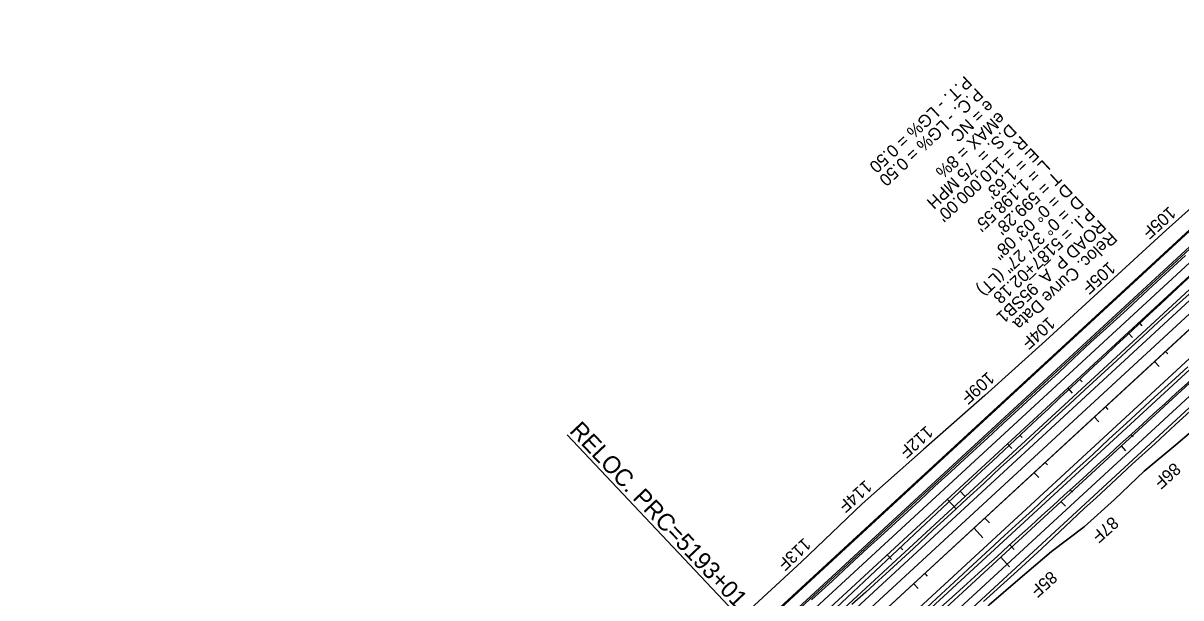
# Model space of a CAD drawing. Extents: x 2160876 to 2175990, y 601436 to 618246.
# Drawn here: x 2169726 to 2171138, y 612405 to 613107 of the extents above; entities that cross this region are included whole.
import ezdxf

# ---------------------------------------------------------------- set-up
doc = ezdxf.new("R2010")
doc.units = 0
for name, color, linetype in [('BNDY-ADJ', 7, 'Continuous'), ('BNDY-ADJ-TXT', 7, 'Continuous'), ('EX-UTIL-ELEC-TXT', 7, 'Continuous'), ('GN_Transparent 80', 7, 'Continuous'), ('RD_DTM_Major2', 7, 'Continuous'), ('RD_EX_BldgApp_Sign', 7, 'Continuous'), ('RD_EX_BldgApp_Steps', 7, 'Continuous'), ('RD_EX_Fence_Gate', 7, 'Continuous'), ('RD_EX_RW', 7, 'Continuous'), ('RD_HC_Cl', 7, 'Continuous'), ('RD_TX_RoadID', 7, 'Continuous')]:
    doc.layers.add(name, color=color, linetype=linetype)

msp = doc.modelspace()

# ---------------------------------------------------------------- linework, layer by layer
at = {"layer": 'BNDY-ADJ'}
msp.add_line((2172239.9, 613739.9), (2163704.8, 605858.6), dxfattribs=at)
at = {"layer": 'BNDY-ADJ-TXT'}
for p, q in [((2172207.3, 613775.1), (2170395.2, 612101.8)), ((2172272.5, 613704.6), (2170460.3, 612031.3))]:
    msp.add_line(p, q, dxfattribs=at)
at = {"layer": 'EX-UTIL-ELEC-TXT'}
for p, q in [((2172179.3, 613805.5), (2170367.1, 612132.2)), ((2172180, 613804.8), (2170367.8, 612131.4)), ((2172199.2, 613784), (2170387, 612110.6)), ((2172207.3, 613775.1), (2170395.2, 612101.8)), ((2172215.5, 613766.3), (2170403.3, 612093)), ((2172264.3, 613713.4), (2170452.2, 612040.1)), ((2172272.5, 613704.6), (2170460.3, 612031.3)), ((2172261.1, 613677.8), (2170468.4, 612022.5))]:
    msp.add_line(p, q, dxfattribs=at)
at = {"layer": 'GN_Transparent 80'}
for p, q in [((2172189.5, 613794.5), (2170377.3, 612121.1)), ((2172191, 613792.8), (2170378.9, 612119.4))]:
    msp.add_line(p, q, dxfattribs=at)
at = {"layer": 'RD_DTM_Major2'}
for p, q in [((2171106.4, 612693.2), (2171111.8, 612687.3)), ((2171032.9, 612625.4), (2171038.4, 612619.5)), ((2170959.5, 612557.5), (2170964.9, 612551.7)), ((2170886, 612489.7), (2170896.9, 612477.9)), ((2170812.5, 612421.9), (2170818, 612416))]:
    msp.add_line(p, q, dxfattribs=at)
at = {"layer": 'RD_EX_BldgApp_Sign'}
msp.add_line((2170418.2, 612076.8), (2171614.4, 613181.4), dxfattribs=at)
at = {"layer": 'RD_EX_BldgApp_Steps'}
for p, q in [((2172672.7, 614139.6), (2163700.6, 605854.7)), ((2171088.2, 612739.8), (2171090.9, 612736.9)), ((2171119.8, 612705.6), (2171122.5, 612702.7)), ((2171015.1, 612671.5), (2171017.8, 612668.6)), ((2171046.4, 612637.8), (2171049.1, 612634.8)), ((2170389.5, 612603.9), (2170649.6, 612328.2)), ((2170942.1, 612603.2), (2170944.8, 612600.3)), ((2171077.5, 612604), (2171080.1, 612601.1)), ((2170972.9, 612569.9), (2170975.6, 612567)), ((2170869.2, 612534.8), (2170874.6, 612529)), ((2171003.5, 612536.7), (2171006.2, 612533.7)), ((2170899.4, 612502.1), (2170904.9, 612496.2)), ((2170796.3, 612466.3), (2170799, 612463.4)), ((2170929.6, 612469.4), (2170935, 612463.5)), ((2170826, 612434.2), (2170828.7, 612431.3))]:
    msp.add_line(p, q, dxfattribs=at)
for centre, start, end in [((2246150.8, 532330.8), 132.719474, 133.343763), ((2096943.5, 693870), 312.103138, 312.719474)]:
    msp.add_arc(centre, 110000, start, end, dxfattribs=at)
at = {"layer": 'RD_EX_Fence_Gate'}
for p, q in [((2171194.8, 612920.4), (2171120.6, 612853.6)), ((2171120.6, 612853.6), (2171047, 612786.1)), ((2171047, 612786.1), (2170973.3, 612718.7)), ((2170973.3, 612718.7), (2170899.3, 612651.6)), ((2170899.3, 612651.6), (2170824.3, 612585.7)), ((2170824.3, 612585.7), (2170749.7, 612519.3)), ((2170749.7, 612519.3), (2170675.7, 612448.7)), ((2170675.7, 612448.7), (2170602.4, 612380.9))]:
    msp.add_line(p, q, dxfattribs=at)
msp.add_lwpolyline([(2171170.3, 612624.1), (2171132.3, 612591.5), (2171093.8, 612559.5), (2171057.6, 612524.9), (2171020.5, 612491.5), (2170980.4, 612461.2), (2170942.5, 612428.5), (2170904.5, 612395.9), (2170868.6, 612361.2), (2170832.6, 612326.4), (2170796, 612292.4), (2170759.1, 612258.7), (2170724.9, 612221.9), (2170684.4, 612192.1), (2170653.3, 612152.1), (2170617.1, 612117.6), (2170580.6, 612083.5), (2170544, 612049.4), (2170507.9, 612014.8), (2170472.7, 611979.1), (2170437.2, 611943.9), (2170400.6, 611909.8), (2170363.7, 611876.2)], dxfattribs=at)
at = {"layer": 'RD_EX_RW'}
for p, q in [((2171194.8, 612920.4), (2171120.6, 612853.6)), ((2171120.6, 612853.6), (2171047, 612786.1)), ((2171047, 612786.1), (2170973.3, 612718.7)), ((2170973.3, 612718.7), (2170899.3, 612651.6)), ((2170899.3, 612651.6), (2170824.3, 612585.7)), ((2170824.3, 612585.7), (2170749.7, 612519.3)), ((2170749.7, 612519.3), (2170675.7, 612448.7)), ((2170675.7, 612448.7), (2170602.4, 612380.9))]:
    msp.add_line(p, q, dxfattribs=at)
for points in [[(2170687.8, 612402), (2170713.1, 612425.2), (2170733.8, 612444.4), (2170756.2, 612465.2), (2170776, 612483.4), (2170795.4, 612501.2), (2170819.8, 612523.6), (2170838.3, 612540.9), (2170858.1, 612558.9), (2170879.7, 612578.7), (2170902.8, 612599.9), (2170921.7, 612617.6), (2170945, 612639.2), (2170967.2, 612659.4), (2170989.2, 612679.6), (2171007.5, 612696.9), (2171028.2, 612716.4), (2171047.6, 612734.1), (2171072.8, 612757), (2171098.7, 612780.9), (2171119.8, 612800.3), (2171144.1, 612822.7)], [(2171148.4, 612775.7), (2171132.9, 612761.7), (2171110.9, 612741.4), (2171092.4, 612724.2), (2171077.7, 612711), (2171060.1, 612694.7), (2171040.7, 612676.8), (2171021.1, 612658.5), (2171002.5, 612641.1), (2170984.4, 612624.6), (2170967.3, 612608.5), (2170951.1, 612593.7), (2170936.5, 612580.2), (2170918.7, 612564.1), (2170897.8, 612544.3), (2170877.3, 612525.5), (2170858.2, 612507.6), (2170836.2, 612487.5), (2170812.1, 612465), (2170782.9, 612438.2), (2170769.4, 612425.8), (2170753.8, 612411.6), (2170736.9, 612396.3)], [(2170828.4, 612392.8), (2170846.1, 612409.2), (2170867.2, 612428.7), (2170884.4, 612444.9), (2170905.4, 612464.1), (2170923.4, 612480.8), (2170941, 612497), (2170957.2, 612511.8), (2170974.6, 612528), (2170992, 612543.9), (2171011.1, 612561.7), (2171030.9, 612579.9), (2171050.7, 612598.3), (2171072, 612618), (2171088.7, 612633.4), (2171106.2, 612649.7), (2171127, 612668.6), (2171146.7, 612686.8)], [(2171168.6, 612649.9), (2171131.4, 612615.9), (2171107.2, 612593.3), (2171078.9, 612567.8), (2171053.2, 612544), (2171034.6, 612526.4), (2171020.7, 612514), (2171004.7, 612498.6), (2170983.3, 612478.6), (2170968.6, 612464.9), (2170939.1, 612437.7), (2170922.2, 612422.5), (2170897.7, 612400.1)], [(2170363.7, 611876.2), (2170400.6, 611909.8), (2170437.2, 611943.9), (2170472.7, 611979.1), (2170507.9, 612014.8), (2170544, 612049.4), (2170580.6, 612083.5), (2170617.1, 612117.6), (2170653.3, 612152.1), (2170684.4, 612192.1), (2170724.9, 612221.9), (2170759.1, 612258.7), (2170796, 612292.4), (2170832.6, 612326.4), (2170868.6, 612361.2), (2170904.5, 612395.9), (2170942.5, 612428.5), (2170980.4, 612461.2), (2171020.5, 612491.5), (2171057.6, 612524.9), (2171093.8, 612559.5), (2171132.3, 612591.5), (2171170.3, 612624.1)]]:
    msp.add_lwpolyline(points, dxfattribs=at)
at = {"layer": 'RD_HC_Cl'}
for p, q in [((2171073.9, 612728.5), (2171079.3, 612722.6)), ((2171000.4, 612660.7), (2171005.8, 612654.8)), ((2170926.9, 612592.8), (2170932.3, 612586.9)), ((2171065.5, 612590.1), (2171070.9, 612584.2)), ((2170853.4, 612525), (2170864.3, 612513.2)), ((2170992, 612522.3), (2170997.5, 612516.4)), ((2170780, 612457.1), (2170785.4, 612451.3)), ((2170918.6, 612454.4), (2170929.4, 612442.7))]:
    msp.add_line(p, q, dxfattribs=at)
at = {"layer": 'RD_TX_RoadID'}
for p, q in [((2172191, 613792.8), (2170378.9, 612119.4)), ((2172287.4, 613688.4), (2170475.2, 612015.1)), ((2171794.8, 613364.3), (2170410.1, 612085.6)), ((2171830.1, 613326.1), (2170445.4, 612047.4))]:
    msp.add_line(p, q, dxfattribs=at)

# ---------------------------------------------------------------- texts
at = {"layer": 'RD_EX_BldgApp_Steps'}
for s, height, rotation, p in [('P.T. - LG% = 0.50', 15, 222.9633, (2170874.9, 613043)), ('P.C. - LG% = 0.50', 15, 222.9633, (2170888.5, 613028.4)), ('e = NC', 15, 222.9633, (2170902.2, 613013.8)), ('D.S. =  75 MPH', 15, 222.9633, (2170929.4, 612984.5)), ('eMAX = 8%', 15, 222.9633, (2170915.8, 612999.1)), ("R = 110,000.00'", 15, 222.9633, (2170943, 612969.9)), ("E = 1.63'", 15, 222.9633, (2170956.7, 612955.2)), ("L = 1,198.55'", 15, 222.9633, (2170970.3, 612940.6)), ("T = 599.28'", 15, 222.9633, (2170983.9, 612926)), ('D = 0° 03\' 08"', 15, 222.9633, (2170997.6, 612911.3)), ('D', 15, 222.9633, (2171011.2, 612896.7)), ('    = 0° 37\' 27" (LT)', 15, 222.9633, (2171011.2, 612896.7)), ('P.I. = 5187+02.18', 15, 222.9633, (2171024.8, 612882.1)), ('ROAD P_A_95SB1', 15, 222.9633, (2171038.5, 612867.4)), ('Reloc. Curve Data', 15, 222.9633, (2171052.1, 612852.8)), ('RELOC. PRC=5193+01.45', 21, 313.3438, (2170391.4, 612607.7))]:
    msp.add_text(s, height=height, rotation=rotation, dxfattribs=at).set_placement(p)
at = {"layer": 'RD_EX_Fence_Gate'}
for s, rotation, p in [('105F', 222.2037, (2171124, 612883.6)), ('105F', 222.1253, (2171050.4, 612816.1)), ('104F', 222.0468, (2170976.8, 612748.7)), ('109F', 221.9683, (2170902.8, 612681.7)), ('112F', 221.8898, (2170827.8, 612615.8)), ('86F', 222.0468, (2171129.9, 612570.7)), ('114F', 221.8113, (2170753.3, 612549.3)), ('87F', 221.9683, (2171054.1, 612504.9)), ('113F', 222.9825, (2170678.6, 612478.8)), ('85F', 221.8898, (2170979.3, 612438.3))]:
    msp.add_text(s, height=15, rotation=rotation, dxfattribs=at).set_placement(p)

doc.saveas('drawing.dxf')
